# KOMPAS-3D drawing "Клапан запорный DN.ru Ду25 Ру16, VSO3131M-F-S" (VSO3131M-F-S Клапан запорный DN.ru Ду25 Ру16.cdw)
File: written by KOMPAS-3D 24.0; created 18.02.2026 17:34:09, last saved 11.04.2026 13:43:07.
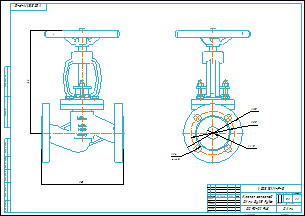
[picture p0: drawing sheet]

Document properties: Автор: R2D2; Форматы листов документа: A2; Полное имя файла: VSO3131M-F-S Клапан запорный DN.ru Ду25 Ру16.m3d; Масса: 5.1; Наименование: Клапан запорный DN.ru Ду25 Ру16; Количество листов документа: 1; Примечание: D090-02948

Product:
- Part/product: Клапан запорный DN.ru Ду25 Ру16  | designation VSO3131M-F-S
    Масса: 5.1
    Раздел спецификации: Прочие изделия
    Примечание: D090-02948

Views: Проекционный вид 2
Referenced files in E:\Работа\Зайцев\VSO3131M-F-S Клапан запорный DN.ru Ду15-100 Ру40\DN25\: VSO3131M-F-S Клапан запорный DN.ru Ду25 Ру40.m3d
Referenced files in E:\Работа\Зайцев\Для компаса\: чертеж DN.ru А3.cdt
Referenced files in E:\Работа\Зайцев\VSO3131M-F-S Клапан запорный DN.ru Ду15-100 Ру16\DN25\: VSO3131M-F-S Клапан запорный DN.ru Ду25 Ру16.m3d
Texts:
  VSO3131M-F-S
  чертеж DN.ru А3.cdt
  Клапан запорный
  DN.ru Ду25 Ру16
  Клапан запорный DN.ru Ду25 Ру16
  VSO3131M-F-S Клапан запорный DN.ru Ду25 Ру16
Dimensions and other numbers on the sheet: 0; 3; 4; 115; 85; 25; 14; 4 отв.; 1; 1:1; 2; 5,1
